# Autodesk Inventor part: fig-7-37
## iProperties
Shininess: 77.0
Length Units: 11269
Angle Units: 11279
Time Units: 11290
Mass Units: 11283
Length Display Precision: 3
Angle Display Precision: 2
Created: 2002-01
Part Number: fig-7-37
Document SubType Name: Modeling
Designer: ***
Density: 1 g/cm^3
Density: 0.0
Volumn: 0.0
Area: 0.0
PropertySet Name: Model Information
Control State: 0
Master: False
Checked Out: False
Author: ***
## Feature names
1. Extrusion1
2. Fillet1
3. Extrusion2
4. Extrusion3
5. Chamfer1
